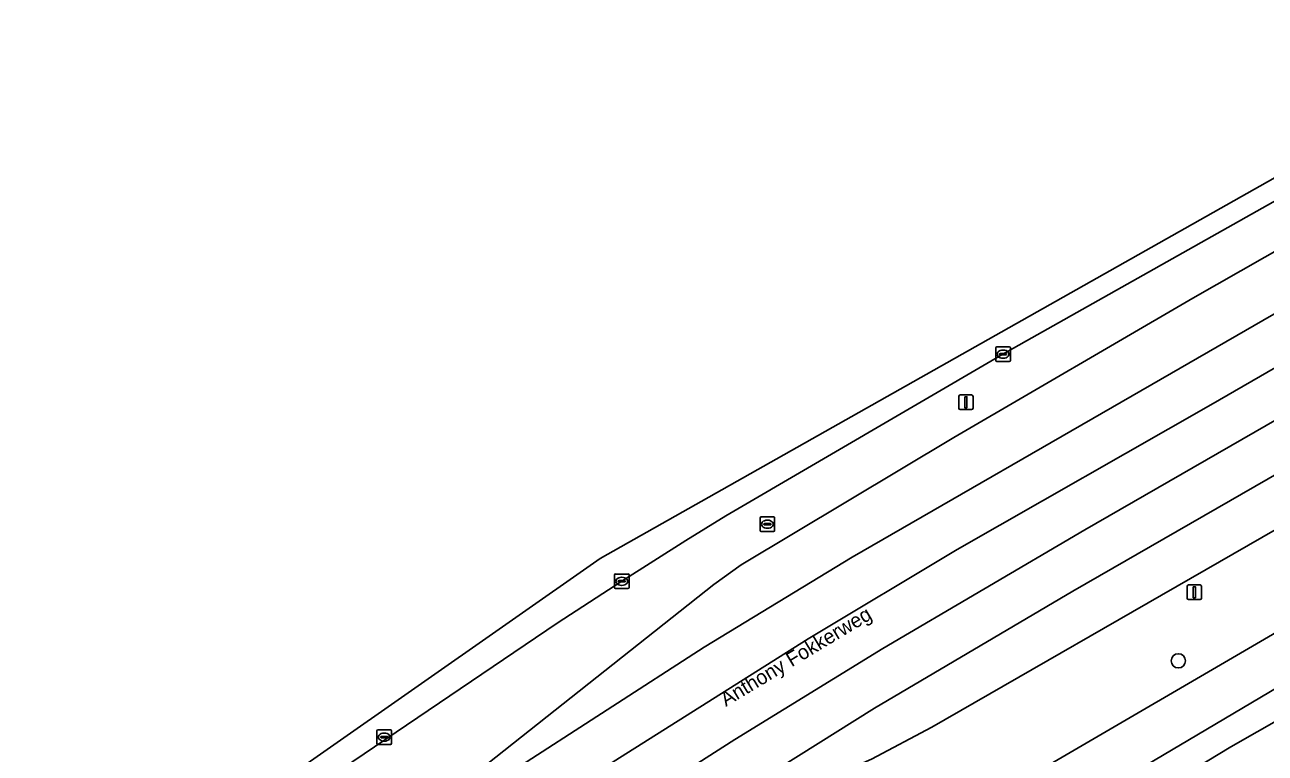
# Model space of a CAD drawing. Extents: x 156502 to 159075, y 384229 to 386100.
# Drawn here: x 157002.7 to 157087.9, y 386035.7 to 386085.7 of the extents above; entities that cross this region are included whole.
import ezdxf

# ---------------------------------------------------------------- set-up
doc = ezdxf.new("R2010")
doc.units = 0
for name, color, linetype in [('IMGEO_Berm_groen', 7, 'Continuous'), ('IMGEO_Boom', 7, 'Continuous'), ('IMGEO_Fietspad_gesloten', 7, 'Continuous'), ('IMGEO_Groenvoorziening', 7, 'Continuous'), ('IMGEO_Hek', 7, 'Continuous'), ('IMGEO_Kolk', 7, 'Continuous'), ('IMGEO_Lichtmast', 7, 'Continuous'), ('IMGEO_Openbare_ruimte_label', 7, 'Continuous'), ('IMGEO_Rijbaan_regionaal_gesloten', 7, 'Continuous'), ('IMGEO_Rioolput', 7, 'Continuous'), ('IMGEO_Verkeersbordpaal', 7, 'Continuous')]:
    doc.layers.add(name, color=color, linetype=linetype)

msp = doc.modelspace()

# ---------------------------------------------------------------- linework, layer by layer
at = {"layer": 'IMGEO_Berm_groen'}
for points in [[(157072.063, 386034.271), (157088.994, 386044.123), (157155.519, 386082.013)], [(157093.929, 386076.579), (157069.925, 386063.065), (157050.884, 386051.964), (157048.122, 386050.274), (157043.719, 386047.465), (157039.286, 386044.593), (157015.666, 386028.614), (157010.597, 386024.976), (157005.574, 386021.288), (157000, 386017.067), (156991.241, 386010.244), (156984.669, 386004.968), (156979.094, 386000.375), (156978.642, 386000), (156974.489, 385996.551), (156954.574, 385978.635), (156942.123, 385966.263), (156938.842, 385963.097), (156938.555, 385962.82), (156941.597, 385957.642), (156942.296, 385957.494)], [(157050.042, 386047.238), (157051.93, 386048.596), (157066.544, 386057.335), (157082.968, 386066.912), (157096.002, 386074.336)], [(157124.356, 386071.514), (157065.043, 386037.45), (157060.887, 386035.244), (157046.143, 386028.726), (157042.85, 386026.929), (157027.314, 386016.727), (157014.962, 386008.38), (157001.907, 385999.125)], [(157021.884, 386025.104), (157024.165, 386026.762), (157050.042, 386047.238)]]:
    msp.add_lwpolyline(points, dxfattribs=at)
at = {"layer": 'IMGEO_Boom'}
msp.add_circle((157081.974, 386042), 0.489, dxfattribs=at)
at = {"layer": 'IMGEO_Fietspad_gesloten'}
msp.add_lwpolyline([(157073.59, 386031.17), (157090.661, 386041.292), (157160.05, 386080.464), (157161.641, 386081.37), (157157.693, 386083.251), (157155.519, 386082.013), (157088.994, 386044.123), (157072.063, 386034.271)], dxfattribs=at)
at = {"layer": 'IMGEO_Groenvoorziening'}
for points in [[(157061.311, 386021.393), (157085.574, 386036.103), (157115.223, 386052.978), (157120.284, 386055.801), (157152.797, 386073.936), (157157.01, 386076.109), (157157.203, 386076.568), (157157.67, 386077.678), (157164.639, 386079.76), (157161.641, 386081.37), (157160.05, 386080.464), (157090.661, 386041.292), (157073.59, 386031.17)], [(157152.797, 386073.936), (157120.284, 386055.801), (157115.223, 386052.978), (157085.574, 386036.103), (157061.311, 386021.393), (157035.37, 386004.621), (157028.46, 386000), (157018.541, 385993.367), (157009.209, 385986.533), (157000, 385979.428), (156983.37, 385965.891), (156973.181, 385956.868), (156962.504, 385946.935), (156954.711, 385939.318), (157000, 385861.546)]]:
    msp.add_lwpolyline(points, dxfattribs=at)
at = {"layer": 'IMGEO_Hek'}
msp.add_lwpolyline([(157120.284, 386055.801), (157115.223, 386052.978), (157085.574, 386036.103), (157061.311, 386021.393), (157035.37, 386004.621), (157028.46, 386000)], dxfattribs=at)
at = {"layer": 'IMGEO_Kolk'}
for p, q in [((157069.429, 386062.638), (157069.429, 386063.49)), ((157069.504, 386063.564), (157070.356, 386063.564)), ((157069.917, 386063.344), (157069.942, 386063.344)), ((157070.43, 386063.49), (157070.43, 386062.638)), ((157070.356, 386062.564), (157069.504, 386062.564)), ((157069.688, 386063.058), (157069.688, 386063.07)), ((157070.126, 386063.021), (157069.728, 386063.021)), ((157069.731, 386063.107), (157070.129, 386063.107)), ((157069.94, 386062.784), (157069.915, 386062.784)), ((157070.172, 386063.07), (157070.172, 386063.058)), ((157043.222, 386047.038), (157043.222, 386047.89)), ((157043.297, 386047.964), (157044.149, 386047.964)), ((157044.223, 386047.89), (157044.223, 386047.038)), ((157043.481, 386047.458), (157043.481, 386047.47)), ((157043.919, 386047.421), (157043.521, 386047.421)), ((157043.524, 386047.507), (157043.922, 386047.507)), ((157043.733, 386047.184), (157043.708, 386047.184)), ((157043.71, 386047.744), (157043.735, 386047.744)), ((157043.965, 386047.47), (157043.965, 386047.458)), ((157044.149, 386046.964), (157043.297, 386046.964)), ((157026.899, 386036.334), (157026.899, 386037.186)), ((157026.974, 386037.26), (157027.826, 386037.26)), ((157027.201, 386036.803), (157027.599, 386036.803)), ((157027.387, 386037.04), (157027.412, 386037.04)), ((157027.9, 386037.186), (157027.9, 386036.334)), ((157027.826, 386036.26), (157026.974, 386036.26)), ((157027.158, 386036.754), (157027.158, 386036.766)), ((157027.596, 386036.717), (157027.198, 386036.717)), ((157027.41, 386036.48), (157027.385, 386036.48)), ((157027.642, 386036.766), (157027.642, 386036.754))]:
    msp.add_line(p, q, dxfattribs=at)
for points in [[(157069.429, 386062.638), (157069.429, 386063.49)], [(157069.504, 386063.564), (157070.356, 386063.564)], [(157070.43, 386063.49), (157070.43, 386062.638)], [(157070.356, 386062.564), (157069.504, 386062.564)], [(157043.222, 386047.038), (157043.222, 386047.89)], [(157043.297, 386047.964), (157044.149, 386047.964)], [(157044.223, 386047.89), (157044.223, 386047.038)], [(157044.149, 386046.964), (157043.297, 386046.964)], [(157026.899, 386036.334), (157026.899, 386037.186)], [(157026.974, 386037.26), (157027.826, 386037.26)], [(157027.9, 386037.186), (157027.9, 386036.334)], [(157027.826, 386036.26), (157026.974, 386036.26)]]:
    msp.add_lwpolyline(points, dxfattribs=at)
for centre, radius, start, end in [((157069.506, 386063.488), 0.0765, 91.55205, 178.44795), ((157069.506, 386063.488), 0.0765, 91.55205, 178.44795), ((157070.354, 386063.488), 0.0765, 1.55205, 88.44795), ((157070.354, 386063.488), 0.0765, 1.55205, 88.44795), ((157069.506, 386062.64), 0.0765, 181.55205, 268.44795), ((157069.506, 386062.64), 0.0765, 181.55205, 268.44795), ((157069.728, 386063.067), 0.0403, 85.87752, 175.75265), ((157069.725, 386063.057), 0.0366, 178.93798, 274.71019), ((157070.129, 386063.064), 0.043, 264.86636, 352.45326), ((157070.133, 386063.069), 0.0386, 1.73085, 96.63898), ((157070.354, 386062.64), 0.0765, 271.55205, 358.44795), ((157070.354, 386062.64), 0.0765, 271.55205, 358.44795), ((157043.299, 386047.888), 0.0765, 91.55205, 178.44795), ((157043.299, 386047.888), 0.0765, 91.55205, 178.44795), ((157044.147, 386047.888), 0.0765, 1.55205, 88.44795), ((157044.147, 386047.888), 0.0765, 1.55205, 88.44795), ((157043.299, 386047.04), 0.0765, 181.55205, 268.44795), ((157043.299, 386047.04), 0.0765, 181.55205, 268.44795), ((157043.521, 386047.467), 0.0403, 85.87752, 175.75265), ((157043.518, 386047.457), 0.0366, 178.93798, 274.71019), ((157043.922, 386047.464), 0.043, 264.86636, 352.45326), ((157043.926, 386047.469), 0.0386, 1.73085, 96.63898), ((157044.147, 386047.04), 0.0765, 271.55205, 358.44795), ((157044.147, 386047.04), 0.0765, 271.55205, 358.44795), ((157026.976, 386037.184), 0.0765, 91.55205, 178.44795), ((157026.976, 386037.184), 0.0765, 91.55205, 178.44795), ((157027.198, 386036.763), 0.0403, 85.87752, 175.75265), ((157027.603, 386036.765), 0.0386, 1.73085, 96.63898), ((157027.824, 386037.184), 0.0765, 1.55205, 88.44795), ((157027.824, 386037.184), 0.0765, 1.55205, 88.44795), ((157026.976, 386036.336), 0.0765, 181.55205, 268.44795), ((157026.976, 386036.336), 0.0765, 181.55205, 268.44795), ((157027.195, 386036.753), 0.0366, 178.93798, 274.71019), ((157027.599, 386036.76), 0.043, 264.86636, 352.45326), ((157027.824, 386036.336), 0.0765, 271.55205, 358.44795), ((157027.824, 386036.336), 0.0765, 271.55205, 358.44795)]:
    msp.add_arc(centre, radius, start, end, dxfattribs=at)
for centre, major_axis, ratio, start_param, end_param in [((157069.916, 386063.064), (-0.387, 0.002), 0.722429, 4.712389, 7.853982), ((157069.941, 386063.064), (-0.39, 0.002), 0.717154, 1.570796, 4.712389), ((157043.709, 386047.464), (-0.387, 0.002), 0.722429, 4.712389, 7.853982), ((157043.734, 386047.464), (-0.39, 0.002), 0.717154, 1.570796, 4.712389), ((157027.386, 386036.76), (-0.387, 0.002), 0.722429, 4.712389, 7.853982), ((157027.411, 386036.76), (-0.39, 0.002), 0.717154, 1.570796, 4.712389)]:
    msp.add_ellipse(centre, major_axis=major_axis, ratio=ratio, start_param=start_param, end_param=end_param, dxfattribs=at)
at = {"layer": 'IMGEO_Lichtmast'}
for p, q in [((157082.579, 386046.311), (157082.579, 386047.111)), ((157082.579, 386047.111), (157082.579, 386046.311)), ((157082.679, 386047.211), (157083.469, 386047.211)), ((157083.469, 386047.211), (157082.679, 386047.211)), ((157083.569, 386047.111), (157083.569, 386046.311)), ((157083.569, 386046.311), (157083.569, 386047.111)), ((157083.469, 386046.211), (157082.679, 386046.211)), ((157082.679, 386046.211), (157083.469, 386046.211))]:
    msp.add_line(p, q, dxfattribs=at)
msp.add_lwpolyline([(157082.999, 386047.086), (157083.149, 386047.086), (157083.149, 386046.336), (157082.999, 386046.336), (157082.999, 386047.086)], dxfattribs=at)
for centre, start, end in [((157082.679, 386047.111), 90, 180), ((157082.679, 386047.111), 90, 180), ((157083.469, 386047.111), 0, 90), ((157083.469, 386047.111), 360, 90), ((157082.679, 386046.311), 180, 270), ((157082.679, 386046.311), 180, 270), ((157083.469, 386046.311), 270, 0), ((157083.469, 386046.311), 270, 0)]:
    msp.add_arc(centre, 0.1, start, end, dxfattribs=at)
at = {"layer": 'IMGEO_Rijbaan_regionaal_gesloten'}
for points in [[(157100.668, 386072.797), (157117.907, 386082.682), (157116.181, 386085.685), (157112.545, 386083.64), (157096.002, 386074.336), (157082.968, 386066.912), (157066.544, 386057.335), (157051.93, 386048.596), (157050.042, 386047.238), (157024.165, 386026.762), (157029.454, 386029.92), (157036.054, 386034.341), (157049.378, 386042.931), (157059.557, 386049.121), (157080.15, 386060.991)], [(157122.709, 386074.353), (157121.098, 386077.147), (157103.064, 386066.827), (157075.553, 386050.997), (157061.67, 386042.848), (157051.495, 386036.595), (157041.498, 386030.211), (157031.595, 386023.549), (157026.997, 386020.297), (157030.426, 386022.09), (157044.247, 386028.186), (157061.084, 386038.746), (157074.723, 386046.785), (157105.237, 386064.332)], [(157124.356, 386071.514), (157122.709, 386074.353), (157105.237, 386064.332), (157074.723, 386046.785), (157061.084, 386038.746), (157044.247, 386028.186), (157042.85, 386026.929), (157046.143, 386028.726), (157060.887, 386035.244), (157065.043, 386037.45)]]:
    msp.add_lwpolyline(points, close=True, dxfattribs=at)
for points in [[(157119.528, 386079.87), (157117.907, 386082.682), (157100.668, 386072.797), (157080.15, 386060.991), (157059.557, 386049.121), (157049.378, 386042.931), (157036.054, 386034.341), (157029.454, 386029.92), (157024.165, 386026.762), (157021.884, 386025.104)], [(156942.296, 385957.494), (156942.001, 385957.212), (156941.706, 385956.931), (156943.443, 385953.937), (156943.573, 385953.713), (156959.136, 385968.488), (156967.977, 385976.503), (156976.948, 385984.306), (156986.671, 385992.565), (156995.937, 386000.282), (157005.167, 386007.853), (157013.774, 386014.708), (157017.648, 386017.606), (157023.402, 386021.708), (157029.939, 386026.251), (157043.13, 386035.069), (157056.537, 386043.513), (157066.767, 386049.648), (157084.202, 386059.591), (157101.546, 386069.596), (157119.528, 386079.87)], [(157093.26, 386077.811), (157042.234, 386049.037), (157004.035, 386022.317), (156961.157, 385987.156)], [(157000, 386017.067), (157005.574, 386021.288), (157010.597, 386024.976), (157015.666, 386028.614), (157039.286, 386044.593), (157043.719, 386047.465), (157048.122, 386050.274), (157050.884, 386051.964), (157069.925, 386063.065), (157093.929, 386076.579)], [(157101.546, 386069.596), (157084.202, 386059.591), (157066.767, 386049.648), (157056.537, 386043.513), (157043.13, 386035.069), (157029.939, 386026.251), (157023.402, 386021.708), (157017.648, 386017.606), (157013.774, 386014.708), (157005.167, 386007.853), (156995.937, 386000.282)], [(156996.744, 385996.742), (157006.403, 386004.757), (157013.644, 386010.539), (157020.382, 386015.656), (157026.997, 386020.297), (157031.595, 386023.549), (157041.498, 386030.211), (157051.495, 386036.595), (157061.67, 386042.848), (157075.553, 386050.997), (157103.064, 386066.827)]]:
    msp.add_lwpolyline(points, dxfattribs=at)
at = {"layer": 'IMGEO_Rioolput'}
for p, q in [((157053.232, 386050.958), (157053.232, 386051.81)), ((157053.307, 386051.884), (157054.159, 386051.884)), ((157053.491, 386051.378), (157053.491, 386051.39)), ((157053.929, 386051.341), (157053.531, 386051.341)), ((157053.534, 386051.427), (157053.932, 386051.427)), ((157053.72, 386051.664), (157053.745, 386051.664)), ((157053.975, 386051.39), (157053.975, 386051.378)), ((157054.233, 386051.81), (157054.233, 386050.958)), ((157054.159, 386050.884), (157053.307, 386050.884)), ((157053.743, 386051.104), (157053.718, 386051.104))]:
    msp.add_line(p, q, dxfattribs=at)
for points in [[(157053.232, 386050.958), (157053.232, 386051.81)], [(157053.307, 386051.884), (157054.159, 386051.884)], [(157054.233, 386051.81), (157054.233, 386050.958)], [(157054.159, 386050.884), (157053.307, 386050.884)]]:
    msp.add_lwpolyline(points, dxfattribs=at)
for centre, radius, start, end in [((157053.309, 386051.808), 0.0765, 91.55205, 178.44795), ((157053.309, 386051.808), 0.0765, 91.55205, 178.44795), ((157053.531, 386051.387), 0.0403, 85.87752, 175.75265), ((157053.528, 386051.377), 0.0366, 178.93798, 274.71019), ((157053.932, 386051.384), 0.043, 264.86636, 352.45326), ((157053.936, 386051.389), 0.0386, 1.73085, 96.63898), ((157054.157, 386051.808), 0.0765, 1.55205, 88.44795), ((157054.157, 386051.808), 0.0765, 1.55205, 88.44795), ((157053.309, 386050.96), 0.0765, 181.55205, 268.44795), ((157053.309, 386050.96), 0.0765, 181.55205, 268.44795), ((157054.157, 386050.96), 0.0765, 271.55205, 358.44795), ((157054.157, 386050.96), 0.0765, 271.55205, 358.44795)]:
    msp.add_arc(centre, radius, start, end, dxfattribs=at)
for centre, major_axis, ratio, start_param, end_param in [((157053.719, 386051.384), (-0.387, 0.002), 0.722429, 4.712389, 7.853982), ((157053.744, 386051.384), (-0.39, 0.002), 0.717154, 1.570796, 4.712389)]:
    msp.add_ellipse(centre, major_axis=major_axis, ratio=ratio, start_param=start_param, end_param=end_param, dxfattribs=at)
at = {"layer": 'IMGEO_Verkeersbordpaal'}
for p, q in [((157066.88, 386059.363), (157066.88, 386060.163)), ((157066.88, 386060.163), (157066.88, 386059.363)), ((157066.98, 386060.263), (157067.77, 386060.263)), ((157067.77, 386060.263), (157066.98, 386060.263)), ((157067.87, 386060.163), (157067.87, 386059.363)), ((157067.87, 386059.363), (157067.87, 386060.163)), ((157067.77, 386059.263), (157066.98, 386059.263)), ((157066.98, 386059.263), (157067.77, 386059.263))]:
    msp.add_line(p, q, dxfattribs=at)
msp.add_lwpolyline([(157067.3, 386060.138), (157067.45, 386060.138), (157067.45, 386059.388), (157067.3, 386059.388), (157067.3, 386060.138)], dxfattribs=at)
for centre, start, end in [((157066.98, 386060.163), 90, 180), ((157066.98, 386060.163), 90, 180), ((157067.77, 386060.163), 0, 90), ((157067.77, 386060.163), 360, 90), ((157066.98, 386059.363), 180, 270), ((157066.98, 386059.363), 180, 270), ((157067.77, 386059.363), 270, 0), ((157067.77, 386059.363), 270, 0)]:
    msp.add_arc(centre, 0.1, start, end, dxfattribs=at)

# ---------------------------------------------------------------- texts
at = {"layer": 'IMGEO_Openbare_ruimte_label'}
msp.add_text('Anthony Fokkerweg', height=1, rotation=31.05216, dxfattribs=at).set_placement((157050.88, 386038.831))

doc.saveas('drawing.dxf')
